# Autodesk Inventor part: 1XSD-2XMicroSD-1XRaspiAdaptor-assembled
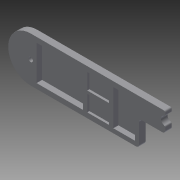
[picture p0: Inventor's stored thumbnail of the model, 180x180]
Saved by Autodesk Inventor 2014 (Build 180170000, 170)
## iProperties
Created: 2015-01
Part Number: 1XSD-2XMicroSD-1XRaspiAdaptor-assembled
Material: Generic
Document SubType Name: Modeling
Designer: Drano
Density: 1 g/cm^3
Appearance: Default
Author: Drano
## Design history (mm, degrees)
derived "raspi adaptor.iam"
thicken "Thicken1" dims "d1" = 1.3, "d2" = 1.3
thicken "Thicken2" dims "d3" = 1, "d4" = 1
thicken "Thicken3" dims "d5" = 1, "d6" = 1
thicken "Thicken4" dims "d7" = 1, "d8" = 1
body "Solid1"
node "backplate.ipt:1" dims "d0" = 10
node "1XSD-2XMicroSD-1XRaspiAdaptor.ipt:1" dims "d0" = 10
node "raspi adaptor.iam_Bodies" dims "d0" = 10
